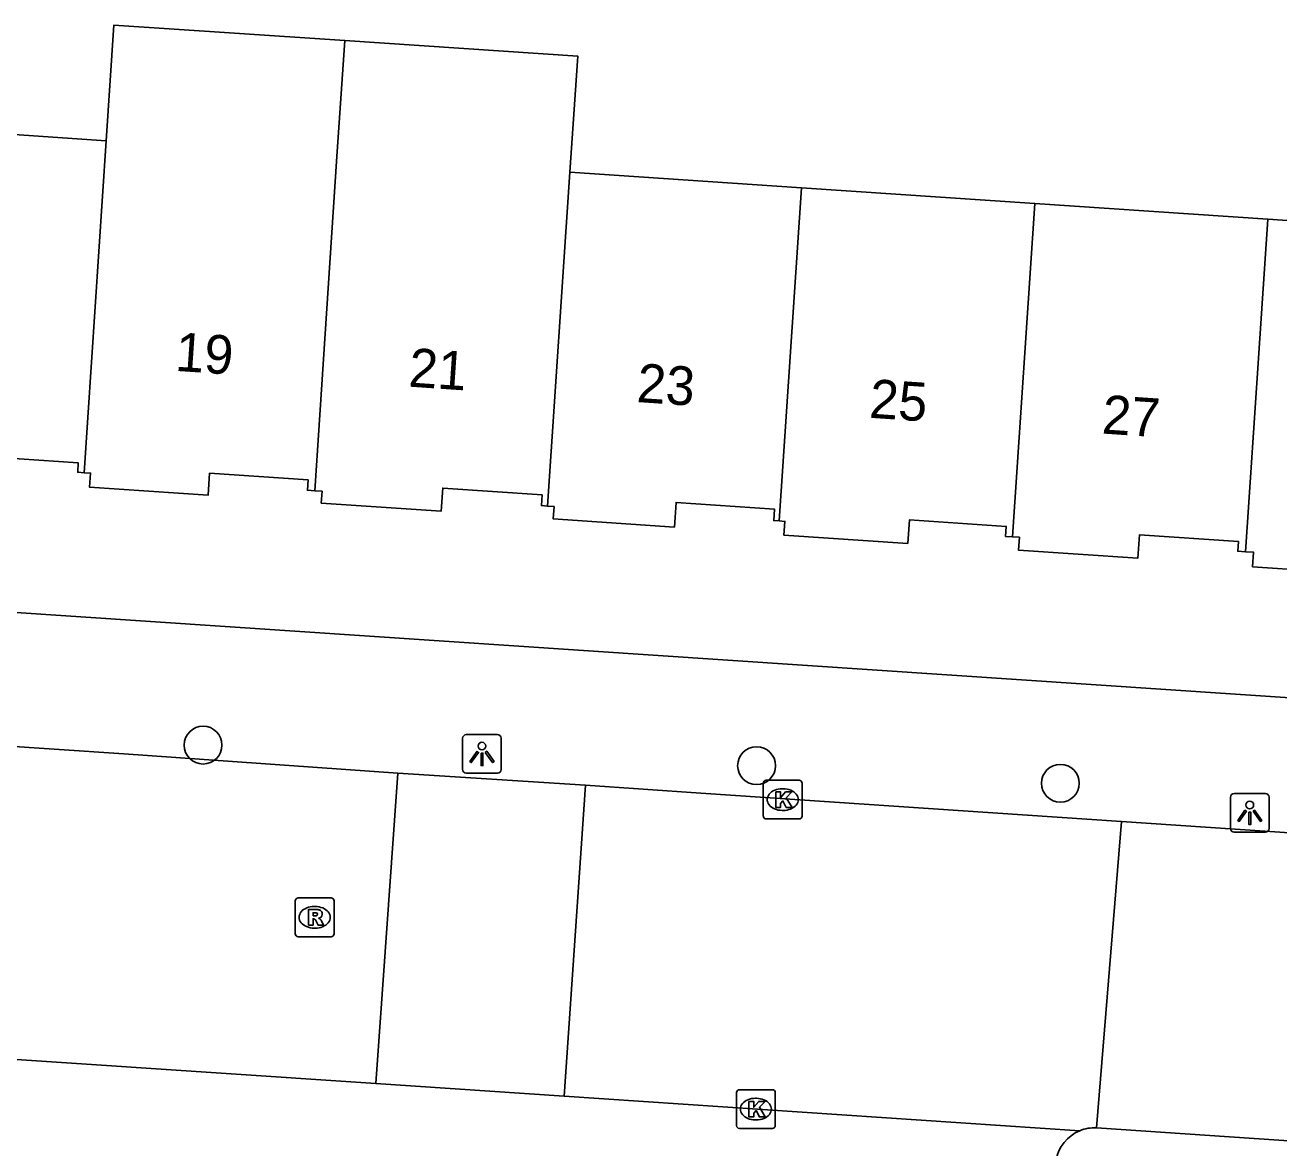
# Model space of a CAD drawing. Extents: x 161848 to 162726, y 385382 to 386521.
# Drawn here: x 162145.56 to 162177.96, y 386153.2 to 386182.2 of the extents above; entities that cross this region are included whole.
import ezdxf

# ---------------------------------------------------------------- set-up
doc = ezdxf.new("R2010")
doc.units = 0
for name, color, linetype in [('IMGEO_Boom', 7, 'Continuous'), ('IMGEO_Kolk', 7, 'Continuous'), ('IMGEO_Lichtpunt', 7, 'Continuous'), ('IMGEO_Pand', 7, 'Continuous'), ('IMGEO_Pand_nummerreeks', 7, 'Continuous'), ('IMGEO_Rijbaan_lokaal_gesloten', 7, 'Continuous'), ('IMGEO_Rijbaan_lokaal_open', 7, 'Continuous'), ('IMGEO_Rioolput', 7, 'Continuous'), ('IMGEO_Voetpad_open', 7, 'Continuous')]:
    doc.layers.add(name, color=color, linetype=linetype)

msp = doc.modelspace()

# ---------------------------------------------------------------- linework, layer by layer
at = {"layer": 'IMGEO_Boom'}
for centre in [(162150.159, 386163.605), (162164.46, 386163.073), (162172.309, 386162.619)]:
    msp.add_circle(centre, 0.489, dxfattribs=at)
at = {"layer": 'IMGEO_Kolk'}
for p, q in [((162164.634, 386161.771), (162164.634, 386162.623)), ((162164.709, 386162.697), (162165.561, 386162.697)), ((162165.122, 386162.477), (162165.147, 386162.477)), ((162165.635, 386162.623), (162165.635, 386161.771)), ((162165.145, 386161.917), (162165.12, 386161.917)), ((162165.561, 386161.697), (162164.709, 386161.697)), ((162164.016, 386154.702), (162164.868, 386154.702)), ((162163.941, 386153.776), (162163.941, 386154.628)), ((162164.429, 386154.482), (162164.454, 386154.482)), ((162164.942, 386154.628), (162164.942, 386153.776)), ((162164.868, 386153.702), (162164.016, 386153.702)), ((162164.452, 386153.922), (162164.427, 386153.922))]:
    msp.add_line(p, q, dxfattribs=at)
for points in [[(162164.634, 386161.771), (162164.634, 386162.623)], [(162164.709, 386162.697), (162165.561, 386162.697)], [(162165.635, 386162.623), (162165.635, 386161.771)], [(162164.955, 386162.397), (162165.078, 386162.397), (162165.078, 386162.246), (162165.208, 386162.397), (162165.372, 386162.397), (162165.226, 386162.246), (162165.379, 386161.997), (162165.227, 386161.997), (162165.142, 386162.161), (162165.078, 386162.094), (162165.078, 386161.997), (162164.955, 386161.997), (162164.955, 386162.397)], [(162165.561, 386161.697), (162164.709, 386161.697)], [(162164.016, 386154.702), (162164.868, 386154.702)], [(162163.941, 386153.776), (162163.941, 386154.628)], [(162164.262, 386154.402), (162164.385, 386154.402), (162164.385, 386154.251), (162164.515, 386154.402), (162164.679, 386154.402), (162164.533, 386154.251), (162164.686, 386154.002), (162164.534, 386154.002), (162164.449, 386154.166), (162164.385, 386154.099), (162164.385, 386154.002), (162164.262, 386154.002), (162164.262, 386154.402)], [(162164.942, 386154.628), (162164.942, 386153.776)], [(162164.868, 386153.702), (162164.016, 386153.702)]]:
    msp.add_lwpolyline(points, dxfattribs=at)
for centre, start, end in [((162164.711, 386162.621), 91.552, 178.448), ((162164.711, 386162.621), 91.552, 178.448), ((162165.559, 386162.621), 1.552, 88.448), ((162165.559, 386162.621), 1.552, 88.448), ((162164.711, 386161.773), 181.552, 268.448), ((162164.711, 386161.773), 181.552, 268.448), ((162165.559, 386161.773), 271.552, 358.448), ((162165.559, 386161.773), 271.552, 358.448), ((162164.018, 386154.626), 91.552, 178.448), ((162164.018, 386154.626), 91.552, 178.448), ((162164.866, 386154.626), 1.552, 88.448), ((162164.866, 386154.626), 1.552, 88.448), ((162164.018, 386153.778), 181.552, 268.448), ((162164.018, 386153.778), 181.552, 268.448), ((162164.866, 386153.778), 271.552, 358.448), ((162164.866, 386153.778), 271.552, 358.448)]:
    msp.add_arc(centre, 0.0765, start, end, dxfattribs=at)
for centre, major_axis, ratio, start_param, end_param in [((162165.121, 386162.197), (-0.387, 0.002), 0.722429, 4.712389, 7.853982), ((162165.146, 386162.197), (-0.39, 0.002), 0.717154, 1.570796, 4.712389), ((162164.428, 386154.202), (-0.387, 0.002), 0.722429, 4.712389, 7.853982), ((162164.453, 386154.202), (-0.39, 0.002), 0.717154, 1.570796, 4.712389)]:
    msp.add_ellipse(centre, major_axis=major_axis, ratio=ratio, start_param=start_param, end_param=end_param, dxfattribs=at)
at = {"layer": 'IMGEO_Lichtpunt'}
for p, q in [((162156.865, 386163.781), (162156.865, 386162.974)), ((162156.865, 386163.781), (162156.865, 386162.974)), ((162157.767, 386163.876), (162156.959, 386163.876)), ((162157.767, 386163.876), (162156.959, 386163.876)), ((162157.861, 386162.974), (162157.861, 386163.781)), ((162157.861, 386162.974), (162157.861, 386163.781)), ((162156.959, 386162.88), (162157.767, 386162.88)), ((162156.959, 386162.88), (162157.767, 386162.88)), ((162176.704, 386162.259), (162176.704, 386161.452)), ((162176.704, 386162.259), (162176.704, 386161.452)), ((162177.606, 386162.354), (162176.798, 386162.354)), ((162177.606, 386162.354), (162176.798, 386162.354)), ((162177.7, 386161.452), (162177.7, 386162.259)), ((162177.7, 386161.452), (162177.7, 386162.259)), ((162176.798, 386161.358), (162177.606, 386161.358)), ((162176.798, 386161.358), (162177.606, 386161.358))]:
    msp.add_line(p, q, dxfattribs=at)
for points in [[(162157.239, 386163.445), (162157.278, 386163.417), (162157.09, 386163.155), (162157.052, 386163.182), (162157.239, 386163.445)], [(162157.341, 386163.397), (162157.388, 386163.397), (162157.388, 386163.075), (162157.341, 386163.075), (162157.341, 386163.397)], [(162157.451, 386163.417), (162157.489, 386163.444), (162157.676, 386163.182), (162157.637, 386163.154), (162157.451, 386163.417)], [(162177.078, 386161.923), (162177.117, 386161.895), (162176.929, 386161.633), (162176.891, 386161.66), (162177.078, 386161.923)], [(162177.18, 386161.875), (162177.227, 386161.875), (162177.227, 386161.553), (162177.18, 386161.553), (162177.18, 386161.875)], [(162177.29, 386161.895), (162177.328, 386161.922), (162177.515, 386161.66), (162177.476, 386161.632), (162177.29, 386161.895)]]:
    msp.add_lwpolyline(points, dxfattribs=at)
for centre in [(162157.364, 386163.579), (162177.203, 386162.057)]:
    msp.add_circle(centre, 0.0994, dxfattribs=at)
for centre, start, end in [((162156.959, 386163.781), 90, 180), ((162156.959, 386163.781), 90, 180), ((162157.767, 386163.781), 0, 90), ((162157.767, 386163.781), 0, 90), ((162156.959, 386162.974), 180, 270), ((162156.959, 386162.974), 180, 270), ((162157.767, 386162.974), 270, 0), ((162157.767, 386162.974), 270, 360), ((162176.798, 386162.259), 90, 180), ((162176.798, 386162.259), 90, 180), ((162177.606, 386162.259), 0, 90), ((162177.606, 386162.259), 0, 90), ((162176.798, 386161.452), 180, 270), ((162176.798, 386161.452), 180, 270), ((162177.606, 386161.452), 270, 0), ((162177.606, 386161.452), 270, 360)]:
    msp.add_arc(centre, 0.0946, start, end, dxfattribs=at)
at = {"layer": 'IMGEO_Pand'}
for points in [[(162153.819, 386181.806), (162150.84, 386182.005), (162147.854, 386182.204), (162147.655, 386179.217)], [(162153.045, 386170.176), (162153.619, 386178.813), (162153.819, 386181.806)], [(162153.819, 386181.806), (162159.839, 386181.404), (162159.636, 386178.406)], [(162141.644, 386179.624), (162147.655, 386179.217)], [(162147.655, 386179.217), (162147.085, 386170.642)], [(162159.636, 386178.406), (162159.062, 386169.779)], [(162159.636, 386178.406), (162165.618, 386178.002)], [(162165.045, 386169.395), (162165.618, 386178.002)], [(162165.618, 386178.002), (162171.645, 386177.594)], [(162171.645, 386177.594), (162171.072, 386168.984)], [(162171.645, 386177.594), (162177.666, 386177.187)], [(162177.095, 386168.6), (162177.666, 386177.187)], [(162177.666, 386177.187), (162183.672, 386176.78)], [(162147.085, 386170.642), (162146.919, 386170.653), (162146.936, 386170.895), (162144.379, 386171.068), (162144.336, 386170.425), (162141.198, 386170.638), (162141.222, 386171.002), (162141.07, 386171.012)], [(162147.085, 386170.642), (162147.252, 386170.631), (162147.227, 386170.266), (162150.289, 386170.059), (162150.328, 386170.627), (162152.872, 386170.455), (162152.854, 386170.189), (162153.045, 386170.176)], [(162159.062, 386169.779), (162158.902, 386169.79), (162158.92, 386170.069), (162156.353, 386170.243), (162156.313, 386169.648), (162153.214, 386169.858), (162153.235, 386170.164), (162153.045, 386170.176)], [(162165.045, 386169.395), (162164.902, 386169.404), (162164.922, 386169.7), (162162.379, 386169.872), (162162.336, 386169.237), (162159.205, 386169.448), (162159.227, 386169.768), (162159.062, 386169.779)], [(162171.072, 386168.984), (162170.893, 386168.996), (162170.911, 386169.252), (162168.407, 386169.421), (162168.366, 386168.816), (162165.168, 386169.032), (162165.192, 386169.385), (162165.045, 386169.395)], [(162177.095, 386168.6), (162176.892, 386168.614), (162176.909, 386168.861), (162174.35, 386169.034), (162174.309, 386168.431), (162171.229, 386168.639), (162171.251, 386168.972), (162171.072, 386168.984)], [(162183.098, 386168.145), (162182.928, 386168.157), (162182.947, 386168.442), (162180.399, 386168.615), (162180.357, 386168.001), (162177.276, 386168.21), (162177.301, 386168.586), (162177.095, 386168.6)]]:
    msp.add_lwpolyline(points, dxfattribs=at)
at = {"layer": 'IMGEO_Rijbaan_lokaal_gesloten'}
for points in [[(162159.485, 386154.535), (162160.041, 386162.567)], [(162160.041, 386162.567), (162163.018, 386162.366), (162173.886, 386161.632)], [(162172.81, 386153.644), (162159.485, 386154.535)]]:
    msp.add_lwpolyline(points, dxfattribs=at)
msp.add_arc((162173.199, 386152.703), 1.018, 87.3391, 112.4369, dxfattribs=at)
at = {"layer": 'IMGEO_Rijbaan_lokaal_open'}
for points in [[(162121.884, 386165.136), (162148.108, 386163.377), (162155.193, 386162.883)], [(162154.622, 386154.86), (162155.193, 386162.883)], [(162155.193, 386162.883), (162160.041, 386162.567)], [(162154.622, 386154.86), (162099.303, 386158.556), (162094.791, 386158.857), (162058.75, 386161.567)], [(162173.246, 386153.72), (162173.886, 386161.632)], [(162173.886, 386161.632), (162181.422, 386161.123)], [(162159.485, 386154.535), (162154.622, 386154.86)], [(162180.75, 386153.209), (162173.246, 386153.72)]]:
    msp.add_lwpolyline(points, dxfattribs=at)
at = {"layer": 'IMGEO_Rioolput'}
for p, q in [((162152.542, 386158.73), (162152.542, 386159.582)), ((162152.617, 386159.656), (162153.469, 386159.656)), ((162153.543, 386159.582), (162153.543, 386158.73)), ((162153.03, 386159.436), (162153.055, 386159.436)), ((162153.053, 386158.876), (162153.028, 386158.876)), ((162153.469, 386158.656), (162152.617, 386158.656))]:
    msp.add_line(p, q, dxfattribs=at)
for points in [[(162152.542, 386158.73), (162152.542, 386159.582)], [(162152.617, 386159.656), (162153.469, 386159.656)], [(162153.543, 386159.582), (162153.543, 386158.73)], [(162153.131, 386159.354), (162152.879, 386159.356), (162152.879, 386158.956)], [(162153.057, 386159.275), (162153.003, 386159.275), (162153.003, 386159.194)], [(162153.003, 386159.194), (162153.055, 386159.194)], [(162152.879, 386158.956), (162153.003, 386158.956), (162153.003, 386159.118), (162153.014, 386159.118)], [(162153.061, 386159.089), (162153.132, 386158.956), (162153.272, 386158.956), (162153.207, 386159.082)], [(162153.469, 386158.656), (162152.617, 386158.656)]]:
    msp.add_lwpolyline(points, dxfattribs=at)
for centre, radius, start, end in [((162152.619, 386159.58), 0.0765, 91.552, 178.448), ((162152.619, 386159.58), 0.0765, 91.552, 178.448), ((162153.467, 386159.58), 0.0765, 1.552, 88.448), ((162153.467, 386159.58), 0.0765, 1.552, 88.448), ((162153.039, 386159.383), 0.19, 274.7715, 282.9687), ((162153.063, 386159.179), 0.0964, 77.0061, 93.1865), ((162153.077, 386159.236), 0.0378, 276.6634, 79.6772), ((162153.13, 386159.244), 0.109, 350.3612, 89.416), ((162153.128, 386159.244), 0.112, 277.5842, 350.9817), ((162153.013, 386159.065), 0.0533, 26.0293, 88.6989), ((162153.112, 386159.029), 0.108, 29.5134, 73.7905), ((162152.619, 386158.732), 0.0765, 181.552, 268.448), ((162152.619, 386158.732), 0.0765, 181.552, 268.448), ((162153.467, 386158.732), 0.0765, 271.552, 358.448), ((162153.467, 386158.732), 0.0765, 271.552, 358.448)]:
    msp.add_arc(centre, radius, start, end, dxfattribs=at)
for centre, major_axis, ratio, start_param, end_param in [((162153.029, 386159.156), (-0.387, 0.002), 0.722429, 4.712389, 7.853982), ((162153.054, 386159.156), (-0.39, 0.002), 0.717154, 1.570796, 4.712389)]:
    msp.add_ellipse(centre, major_axis=major_axis, ratio=ratio, start_param=start_param, end_param=end_param, dxfattribs=at)
at = {"layer": 'IMGEO_Voetpad_open'}
msp.add_lwpolyline([(162122.559, 386168.552), (162206.8, 386162.912)], dxfattribs=at)
msp.add_arc((162173.195, 386152.709), 1.011, 112.3663, 170.6593, dxfattribs=at)

# ---------------------------------------------------------------- texts
at = {"layer": 'IMGEO_Pand_nummerreeks'}
for s, rotation, p in [('19', 356.1325, (162149.421, 386173.274)), ('21', 356.1325, (162155.451, 386172.866)), ('23', 356.1311, (162161.346, 386172.468)), ('25', 356.1311, (162167.355, 386172.062)), ('27', 356.1311, (162173.363, 386171.655))]:
    msp.add_text(s, height=1, rotation=rotation, dxfattribs=at).set_placement(p)

doc.saveas('drawing.dxf')
